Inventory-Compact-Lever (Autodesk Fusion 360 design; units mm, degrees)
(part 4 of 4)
work_plane "WorkPlane66" AlongDistance 54.9 ExtraOffset 0
sketch "Support-free horizontal rail hole roof" plane through (0, 0, 54.9) normal (0, 0, 1) x axis (1, 0, 0)
  line L1 (-28.0908, -83.0908) -> (-28.0908, -86.9092)
  line L2 (-26.1816, -85) -> (-28.0908, -83.0908)
  line L3 (-28.0908, -86.9092) -> (-26.1816, -85)
extrude "Extrude66" cut sketch "Support-free horizontal rail hole roof" along normal blind 9.2
work_plane "WorkPlane67" AlongDistance 54.9 ExtraOffset 0
sketch "Support-free horizontal rail hole roof (1)" plane through (0, 0, 54.9) normal (0, 0, 1) x axis (1, 0, 0)
  line L1 (-28.0908, 86.9092) -> (-28.0908, 83.0908)
  line L2 (-26.1816, 85) -> (-28.0908, 86.9092)
  line L3 (-28.0908, 83.0908) -> (-26.1816, 85)
extrude "Extrude67" cut sketch "Support-free horizontal rail hole roof (1)" along normal blind 9.2
work_plane "WorkPlane61" AlongDistance 54.9 ExtraOffset 0
sketch "Support-free horizontal rail hole roof" plane through (0, 0, 54.9) normal (0, 0, 1) x axis (1, 0, 0)
  line L1 (31.9092, -83.0908) -> (31.9092, -86.9092)
  line L2 (33.8184, -85) -> (31.9092, -83.0908)
  line L3 (31.9092, -86.9092) -> (33.8184, -85)
extrude "Extrude61" cut sketch "Support-free horizontal rail hole roof" along normal blind 9.2
work_plane "WorkPlane62" AlongDistance 54.9 ExtraOffset 0
sketch "Support-free horizontal rail hole roof (1)" plane through (0, 0, 54.9) normal (0, 0, 1) x axis (1, 0, 0)
  line L1 (31.9092, 86.9092) -> (31.9092, 83.0908)
  line L2 (33.8184, 85) -> (31.9092, 86.9092)
  line L3 (31.9092, 83.0908) -> (33.8184, 85)
extrude "Extrude62" cut sketch "Support-free horizontal rail hole roof (1)" along normal blind 9.2
work_plane "WorkPlane14" AlongDistance 4 ExtraOffset 0
sketch "Reinforced roof over support-free pivot bore" plane through (4, 0, 0) normal (1, 0, 0) x axis (0, 0, -1)
  line L1 (-17.9, -29) -> (-17.9, -41)
  line L2 (-20, -29) -> (-17.9, -29)
  line L3 (-20, -41) -> (-20, -29)
  line L4 (-17.9, -41) -> (-20, -41)
extrude "Extrude14" add sketch "Reinforced roof over support-free pivot bore" along normal blind 3
work_plane "WorkPlane15" AlongDistance 4 ExtraOffset 0
sketch "Flat print foot below roller cheek" plane through (4, 0, 0) normal (1, 0, 0) x axis (0, 0, -1)
  line L1 (-6, 6) -> (-6, -6)
  line L2 (-12, 6) -> (-6, 6)
  line L3 (-12, -6) -> (-12, 6)
  line L4 (-6, -6) -> (-12, -6)
extrude "Extrude15" add sketch "Flat print foot below roller cheek" along normal blind 3
work_plane "WorkPlane16" AlongDistance 17 ExtraOffset 0
sketch "Reinforced roof over support-free pivot bore (1)" plane through (17, 0, 0) normal (1, 0, 0) x axis (0, 0, -1)
  line L1 (-17.9, -29) -> (-17.9, -41)
  line L2 (-20, -29) -> (-17.9, -29)
  line L3 (-20, -41) -> (-20, -29)
  line L4 (-17.9, -41) -> (-20, -41)
extrude "Extrude16" add sketch "Reinforced roof over support-free pivot bore (1)" along normal blind 3
work_plane "WorkPlane17" AlongDistance 17 ExtraOffset 0
sketch "Flat print foot below roller cheek (1)" plane through (17, 0, 0) normal (1, 0, 0) x axis (0, 0, -1)
  line L1 (-6, 6) -> (-6, -6)
  line L2 (-12, 6) -> (-6, 6)
  line L3 (-12, -6) -> (-12, 6)
  line L4 (-6, -6) -> (-12, -6)
extrude "Extrude17" add sketch "Flat print foot below roller cheek (1)" along normal blind 3
work_plane "WorkPlane18" AlongDistance 3.9 ExtraOffset 0
sketch "Follower horizontal bore 45 degree roof" plane through (3.9, 0, 0) normal (1, 0, 0) x axis (0, 0, -1)
  line L1 (-14.9345, -32.0655) -> (-14.9345, -37.9345)
  line L2 (-17.869, -35) -> (-14.9345, -32.0655)
  line L3 (-14.9345, -37.9345) -> (-17.869, -35)
extrude "Extrude18" cut sketch "Follower horizontal bore 45 degree roof" along normal blind 16.2
work_plane "WorkPlane19" AlongDistance 3.9 ExtraOffset 0
sketch "Follower horizontal bore 45 degree roof (1)" plane through (3.9, 0, 0) normal (1, 0, 0) x axis (0, 0, -1)
  line L1 (-13.2021, 1.2021) -> (-13.2021, -1.2021)
  line L2 (-14.4042, 0) -> (-13.2021, 1.2021)
  line L3 (-13.2021, -1.2021) -> (-14.4042, 0)
extrude "Extrude19" cut sketch "Follower horizontal bore 45 degree roof (1)" along normal blind 16.2
work_plane "WorkPlane8" AlongDistance 49.65 ExtraOffset 0
sketch "Continuous support beneath lower output prong" plane through (49.65, 0, 0) normal (1, 0, 0) x axis (0, 0, -1)
  line L1 (-57, 2) -> (-57, -2)
  line L2 (-61, 2) -> (-57, 2)
  line L3 (-61, -2) -> (-61, 2)
  line L4 (-57, -2) -> (-61, -2)
extrude "Extrude8" add sketch "Continuous support beneath lower output prong" along normal blind 9
work_plane "WorkPlane11" AlongDistance 9 ExtraOffset 0
sketch "Upright grip head pocket roof" plane through (9, 0, 0) normal (1, 0, 0) x axis (0, 0, -1)
  line L1 (-182.192, -2.192) -> (-182.192, 2.192)
  line L2 (-184.3841, 0) -> (-182.192, -2.192)
  line L3 (-182.192, 2.192) -> (-184.3841, 0)
extrude "Extrude10" cut sketch "Upright grip head pocket roof" along normal blind 16
work_plane "WorkPlane12" AlongDistance 9 ExtraOffset 0
sketch "Upright grip head pocket roof (1)" plane through (9, 0, 0) normal (1, 0, 0) x axis (0, 0, -1)
  line L1 (-192.192, -2.192) -> (-192.192, 2.192)
  line L2 (-194.3841, 0) -> (-192.192, -2.192)
  line L3 (-192.192, 2.192) -> (-194.3841, 0)
extrude "Extrude11" cut sketch "Upright grip head pocket roof (1)" along normal blind 16
work_plane "WorkPlane11" AlongDistance -6.8 ExtraOffset 0
sketch "Shaft half joining insert pocket" plane through (0, -6.8, 0) normal (0, 1, 0) x axis (1, 0, 0)
  circle C1 centre (-15, -65) radius 2
extrude "Extrude11" cut sketch "Shaft half joining insert pocket" along normal blind 6.9
work_plane "WorkPlane12" AlongDistance -0.1 ExtraOffset 0
sketch "Shaft half joining screw clearance" plane through (0, -0.1, 0) normal (0, 1, 0) x axis (1, 0, 0)
  circle C1 centre (-15, -65) radius 1.7
extrude "Extrude12" cut sketch "Shaft half joining screw clearance" along normal blind 6.7
work_plane "WorkPlane13" AlongDistance 3.5 ExtraOffset 0
sketch "Flush shaft joining cap head" plane through (0, 3.5, 0) normal (0, 1, 0) x axis (1, 0, 0)
  circle C1 centre (-15, -65) radius 3.1
extrude "Extrude13" cut sketch "Flush shaft joining cap head" along normal blind 3.1
work_plane "WorkPlane1" AlongDistance -4.5 ExtraOffset 0
sketch "Shaft joining M3x8 -15" plane through (0, -4.5, 0) normal (0, 1, 0) x axis (1, 0, 0)
  circle C1 centre (-15, -65) radius 1.5
extrude "Extrude1" new body sketch "Shaft joining M3x8 -15" along normal blind 8 bodies "HARDWARE Shaft joining M3x8 -15"
work_plane "WorkPlane2" AlongDistance 3.5 ExtraOffset 0
sketch "Button head" plane through (0, 3.5, 0) normal (0, 1, 0) x axis (1, 0, 0)
  circle C1 centre (-15, -65) radius 2.75
extrude "Extrude2" add sketch "Button head" along normal blind 3
work_plane "WorkPlane14" AlongDistance -6.8 ExtraOffset 0
sketch "Shaft half joining insert pocket (1)" plane through (0, -6.8, 0) normal (0, 1, 0) x axis (1, 0, 0)
  circle C1 centre (15, -65) radius 2
extrude "Extrude14" cut sketch "Shaft half joining insert pocket (1)" along normal blind 6.9
work_plane "WorkPlane15" AlongDistance -0.1 ExtraOffset 0
sketch "Shaft half joining screw clearance (1)" plane through (0, -0.1, 0) normal (0, 1, 0) x axis (1, 0, 0)
  circle C1 centre (15, -65) radius 1.7
extrude "Extrude15" cut sketch "Shaft half joining screw clearance (1)" along normal blind 6.7
work_plane "WorkPlane16" AlongDistance 3.5 ExtraOffset 0
sketch "Flush shaft joining cap head (1)" plane through (0, 3.5, 0) normal (0, 1, 0) x axis (1, 0, 0)
  circle C1 centre (15, -65) radius 3.1
extrude "Extrude16" cut sketch "Flush shaft joining cap head (1)" along normal blind 3.1
work_plane "WorkPlane1" AlongDistance -4.5 ExtraOffset 0
sketch "Shaft joining M3x8 15" plane through (0, -4.5, 0) normal (0, 1, 0) x axis (1, 0, 0)
  circle C1 centre (15, -65) radius 1.5
extrude "Extrude1" new body sketch "Shaft joining M3x8 15" along normal blind 8 bodies "HARDWARE Shaft joining M3x8 15"
work_plane "WorkPlane2" AlongDistance 3.5 ExtraOffset 0
sketch "Button head" plane through (0, 3.5, 0) normal (0, 1, 0) x axis (1, 0, 0)
  circle C1 centre (15, -65) radius 2.75
extrude "Extrude2" add sketch "Button head" along normal blind 3
work_plane "WorkPlane17" AlongDistance -6.6 ExtraOffset 0
sketch "Loose alignment key pocket" plane through (-6.6, 0, 0) normal (1, 0, 0) x axis (0, 0, -1)
  line L1 (-61, 1.6) -> (-61, -1.6)
  line L2 (-69, 1.6) -> (-61, 1.6)
  line L3 (-69, -1.6) -> (-69, 1.6)
  line L4 (-61, -1.6) -> (-69, -1.6)
extrude "Extrude17" cut sketch "Loose alignment key pocket" along normal blind 3.2
work_plane "WorkPlane1" AlongDistance -6.5 ExtraOffset 0
sketch "Loose flat printable alignment key" plane through (-6.5, 0, 0) normal (1, 0, 0) x axis (0, 0, -1)
  line L1 (-61.1, 1.5) -> (-61.1, -1.5)
  line L2 (-68.9, 1.5) -> (-61.1, 1.5)
  line L3 (-68.9, -1.5) -> (-68.9, 1.5)
  line L4 (-61.1, -1.5) -> (-68.9, -1.5)
extrude "Extrude1" new body sketch "Loose flat printable alignment key" along normal blind 3 bodies "P28 Shaft alignment key -5"
work_plane "WorkPlane18" AlongDistance 3.4 ExtraOffset 0
sketch "Loose alignment key pocket (1)" plane through (3.4, 0, 0) normal (1, 0, 0) x axis (0, 0, -1)
  line L1 (-61, 1.6) -> (-61, -1.6)
  line L2 (-69, 1.6) -> (-61, 1.6)
  line L3 (-69, -1.6) -> (-69, 1.6)
  line L4 (-61, -1.6) -> (-69, -1.6)
extrude "Extrude18" cut sketch "Loose alignment key pocket (1)" along normal blind 3.2
work_plane "WorkPlane1" AlongDistance 3.5 ExtraOffset 0
sketch "Loose flat printable alignment key" plane through (3.5, 0, 0) normal (1, 0, 0) x axis (0, 0, -1)
  line L1 (-61.1, 1.5) -> (-61.1, -1.5)
  line L2 (-68.9, 1.5) -> (-61.1, 1.5)
  line L3 (-68.9, -1.5) -> (-68.9, 1.5)
  line L4 (-61.1, -1.5) -> (-68.9, -1.5)
extrude "Extrude1" new body sketch "Loose flat printable alignment key" along normal blind 3 bodies "P28 Shaft alignment key 5"
split "Split1" bodies "P05 Shaft upper half"
work_plane "WorkPlane19" AlongDistance -5 ExtraOffset 0
sketch "Direct cap-head rotor clamp seat" plane through (-5, 0, 0) normal (1, 0, 0) x axis (0, 0, -1)
  line L1 (-60, 22.5) -> (-60, 22)
  line L2 (-70, 22.5) -> (-60, 22.5)
  line L3 (-70, 22) -> (-70, 22.5)
  line L4 (-60, 22) -> (-70, 22)
extrude "Extrude19" add sketch "Direct cap-head rotor clamp seat" along normal blind 10
work_plane "WorkPlane20" AlongDistance 21.9 ExtraOffset 0
sketch "Restore rotor screw through raised seat" plane through (0, 21.9, 0) normal (0, 1, 0) x axis (1, 0, 0)
  circle C1 centre (0, -65) radius 1.7
extrude "Extrude20" cut sketch "Restore rotor screw through raised seat" along normal blind 0.7
work_plane "WorkPlane1" AlongDistance -39.35 ExtraOffset 0
sketch "Main shaft cap M3x8 cap head" plane through (-39.35, 0, 0) normal (1, 0, 0) x axis (0, 0, -1)
  circle C1 centre (-65, 0) radius 1.5
extrude "Extrude1" new body sketch "Main shaft cap M3x8 cap head" along normal blind 8 bodies "HARDWARE Main shaft cap M3x8 cap head"
work_plane "WorkPlane2" AlongDistance -42.35 ExtraOffset 0
sketch "Button head" plane through (-42.35, 0, 0) normal (1, 0, 0) x axis (0, 0, -1)
  circle C1 centre (-65, 0) radius 2.75
extrude "Extrude2" add sketch "Button head" along normal blind 3
work_plane "WorkPlane1" AlongDistance 2 ExtraOffset 0
sketch "Cam M3x10 cap head -45" plane through (2, 0, 0) normal (1, 0, 0) x axis (0, 0, -1)
  circle C1 centre (-39.5442, 25.4558) radius 1.5
extrude "Extrude1" new body sketch "Cam M3x10 cap head -45" along normal blind 10 bodies "HARDWARE Cam M3x10 cap head -45"
work_plane "WorkPlane2" AlongDistance 12 ExtraOffset 0
sketch "Button head" plane through (12, 0, 0) normal (1, 0, 0) x axis (0, 0, -1)
  circle C1 centre (-39.5442, 25.4558) radius 2.75
extrude "Extrude2" add sketch "Button head" along normal blind 3
work_plane "WorkPlane1" AlongDistance 2 ExtraOffset 0
sketch "Cam M3x10 cap head 0" plane through (2, 0, 0) normal (1, 0, 0) x axis (0, 0, -1)
  circle C1 centre (-29, 0) radius 1.5
extrude "Extrude1" new body sketch "Cam M3x10 cap head 0" along normal blind 10 bodies "HARDWARE Cam M3x10 cap head 0"
work_plane "WorkPlane2" AlongDistance 12 ExtraOffset 0
sketch "Button head" plane through (12, 0, 0) normal (1, 0, 0) x axis (0, 0, -1)
  circle C1 centre (-29, 0) radius 2.75
extrude "Extrude2" add sketch "Button head" along normal blind 3
work_plane "WorkPlane1" AlongDistance 2 ExtraOffset 0
sketch "Cam M3x10 cap head 45" plane through (2, 0, 0) normal (1, 0, 0) x axis (0, 0, -1)
  circle C1 centre (-39.5442, -25.4558) radius 1.5
extrude "Extrude1" new body sketch "Cam M3x10 cap head 45" along normal blind 10 bodies "HARDWARE Cam M3x10 cap head 45"
work_plane "WorkPlane2" AlongDistance 12 ExtraOffset 0
sketch "Button head" plane through (12, 0, 0) normal (1, 0, 0) x axis (0, 0, -1)
  circle C1 centre (-39.5442, -25.4558) radius 2.75
extrude "Extrude2" add sketch "Button head" along normal blind 3
work_plane "WorkPlane1" AlongDistance 0 ExtraOffset 0
sketch "Roller axle M3x20 cap head" plane through (0, 0, 0) normal (1, 0, 0) x axis (0, 0, -1)
  circle C1 centre (-12, 0) radius 1.5
extrude "Extrude1" new body sketch "Roller axle M3x20 cap head" along normal blind 20 bodies "HARDWARE Roller axle M3x20 cap head"
work_plane "WorkPlane2" AlongDistance 20 ExtraOffset 0
sketch "Button head" plane through (20, 0, 0) normal (1, 0, 0) x axis (0, 0, -1)
  circle C1 centre (-12, 0) radius 2.75
extrude "Extrude2" add sketch "Button head" along normal blind 3
work_plane "WorkPlane1" AlongDistance -36 ExtraOffset 0
sketch "Crossblock M3x20 cap head (-62, -1)" plane through (-36, 0, 0) normal (1, 0, 0) x axis (0, 0, -1)
  circle C1 centre (-53.5, -62) radius 1.5
extrude "Extrude1" new body sketch "Crossblock M3x20 cap head (-62, -1)" along normal blind 20 bodies "HARDWARE Crossblock M3x20 cap head (-62, -1)"
work_plane "WorkPlane2" AlongDistance -39 ExtraOffset 0
sketch "Button head" plane through (-39, 0, 0) normal (1, 0, 0) x axis (0, 0, -1)
  circle C1 centre (-53.5, -62) radius 2.75
extrude "Extrude2" add sketch "Button head" along normal blind 3
work_plane "WorkPlane1" AlongDistance 16 ExtraOffset 0
sketch "Crossblock M3x20 cap head (-62, 1)" plane through (16, 0, 0) normal (1, 0, 0) x axis (0, 0, -1)
  circle C1 centre (-53.5, -62) radius 1.5
extrude "Extrude1" new body sketch "Crossblock M3x20 cap head (-62, 1)" along normal blind 20 bodies "HARDWARE Crossblock M3x20 cap head (-62, 1)"
work_plane "WorkPlane2" AlongDistance 36 ExtraOffset 0
sketch "Button head" plane through (36, 0, 0) normal (1, 0, 0) x axis (0, 0, -1)
  circle C1 centre (-53.5, -62) radius 2.75
extrude "Extrude2" add sketch "Button head" along normal blind 3
work_plane "WorkPlane1" AlongDistance -36 ExtraOffset 0
sketch "Crossblock M3x20 cap head (-70, -1)" plane through (-36, 0, 0) normal (1, 0, 0) x axis (0, 0, -1)
  circle C1 centre (-53.5, -70) radius 1.5
extrude "Extrude1" new body sketch "Crossblock M3x20 cap head (-70, -1)" along normal blind 20 bodies "HARDWARE Crossblock M3x20 cap head (-70, -1)"
work_plane "WorkPlane2" AlongDistance -39 ExtraOffset 0
sketch "Button head" plane through (-39, 0, 0) normal (1, 0, 0) x axis (0, 0, -1)
  circle C1 centre (-53.5, -70) radius 2.75
extrude "Extrude2" add sketch "Button head" along normal blind 3
work_plane "WorkPlane1" AlongDistance 16 ExtraOffset 0
sketch "Crossblock M3x20 cap head (-70, 1)" plane through (16, 0, 0) normal (1, 0, 0) x axis (0, 0, -1)
  circle C1 centre (-53.5, -70) radius 1.5
extrude "Extrude1" new body sketch "Crossblock M3x20 cap head (-70, 1)" along normal blind 20 bodies "HARDWARE Crossblock M3x20 cap head (-70, 1)"
work_plane "WorkPlane2" AlongDistance 36 ExtraOffset 0
sketch "Button head" plane through (36, 0, 0) normal (1, 0, 0) x axis (0, 0, -1)
  circle C1 centre (-53.5, -70) radius 2.75
extrude "Extrude2" add sketch "Button head" along normal blind 3
work_plane "WorkPlane1" AlongDistance 6.5 ExtraOffset 0
sketch "Rotor clamp M3x16 cap head" plane through (0, 6.5, 0) normal (0, 1, 0) x axis (1, 0, 0)
  circle C1 centre (0, -65) radius 1.5
extrude "Extrude1" new body sketch "Rotor clamp M3x16 cap head" along normal blind 16 bodies "HARDWARE Rotor clamp M3x16 cap head"
work_plane "WorkPlane2" AlongDistance 22.5 ExtraOffset 0
sketch "Button head" plane through (0, 22.5, 0) normal (0, 1, 0) x axis (1, 0, 0)
  circle C1 centre (0, -65) radius 2.75
extrude "Extrude2" add sketch "Button head" along normal blind 3
work_plane "WorkPlane20" AlongDistance 3.9 ExtraOffset 0
sketch "Restore axle bore after adding print feet" plane through (3.9, 0, 0) normal (1, 0, 0) x axis (0, 0, -1)
  circle C1 centre (-12, 0) radius 1.7
extrude "Extrude20" cut sketch "Restore axle bore after adding print feet" along normal blind 16.2
work_plane "WorkPlane21" AlongDistance 3.9 ExtraOffset 0
sketch "Restore nut installation recess after print foot" plane through (3.9, 0, 0) normal (1, 0, 0) x axis (0, 0, -1)
  line L1 (-14.9, 1.6743) -> (-12, 3.3486)
  line L2 (-14.9, -1.6743) -> (-14.9, 1.6743)
  line L3 (-12, -3.3486) -> (-14.9, -1.6743)
  line L4 (-9.1, -1.6743) -> (-12, -3.3486)
  line L5 (-9.1, 1.6743) -> (-9.1, -1.6743)
  line L6 (-12, 3.3486) -> (-9.1, 1.6743)
extrude "Extrude21" cut sketch "Restore nut installation recess after print foot" along normal blind 1.6
work_plane "WorkPlane3" AlongDistance 8 ExtraOffset 0
sketch "Retain one mm preload travel before head meets collar" plane through (8, 0, 0) normal (1, 0, 0) x axis (0, 0, -1)
  line L1 (-56, -51) -> (-56, -59)
  line L2 (-57.1, -51) -> (-56, -51)
  line L3 (-57.1, -59) -> (-57.1, -51)
  line L4 (-56, -59) -> (-57.1, -59)
extrude "Extrude3" cut sketch "Retain one mm preload travel before head meets collar" along normal blind 8
work_plane "WorkPlane63" AlongDistance 20.8 ExtraOffset 0
sketch "Clear stocked carriage screw tip beyond insert" plane through (0, 20.8, 0) normal (0, 1, 0) x axis (1, 0, 0)
  circle C1 centre (60.15, -65) radius 1.7
extrude "Extrude63" cut sketch "Clear stocked carriage screw tip beyond insert" along normal blind 0.6
work_plane "WorkPlane64" AlongDistance -21.4 ExtraOffset 0
sketch "Clear stocked carriage screw tip beyond insert (1)" plane through (0, -21.4, 0) normal (0, 1, 0) x axis (1, 0, 0)
  circle C1 centre (60.15, -65) radius 1.7
extrude "Extrude64" cut sketch "Clear stocked carriage screw tip beyond insert (1)" along normal blind 0.6
work_plane "WorkPlane22" AlongDistance -2.5 ExtraOffset 0
sketch "Support-free lower ramp under left inner-race pad" plane through (0, -2.5, 0) normal (0, 1, 0) x axis (1, 0, 0)
  line L1 (8.1, -9.5) -> (7, -9.5)
  line L2 (8.1, -10.7) -> (8.1, -9.5)
  line L3 (7, -9.6) -> (8.1, -10.7)
  line L4 (7, -9.5) -> (7, -9.6)
extrude "Extrude22" cut sketch "Support-free lower ramp under left inner-race pad" along normal blind 5
work_plane "WorkPlane23" AlongDistance -2.5 ExtraOffset 0
sketch "Support-free lower ramp under right inner-race pad" plane through (0, -2.5, 0) normal (0, 1, 0) x axis (1, 0, 0)
  line L1 (17, -9.5) -> (15.9, -9.5)
  line L2 (17, -9.6) -> (17, -9.5)
  line L3 (15.9, -10.7) -> (17, -9.6)
  line L4 (15.9, -9.5) -> (15.9, -10.7)
extrude "Extrude23" cut sketch "Support-free lower ramp under right inner-race pad" along normal blind 5
ground "Pin94"
ground "Pin95"
ground "Pin96"
ground "Pin97"
ground "Pin98"
ground "Pin99"
ground "Pin100"
ground "Pin101"
ground "Pin102"
ground "Pin103"
ground "Pin104"
ground "Pin105"
ground "Pin106"
ground "Pin107"
ground "Pin108"
ground "Pin109"
ground "Pin110"
ground "Pin111"
ground "Pin112"
ground "Pin113"
ground "Pin114"
ground "Pin115"
ground "Pin116"
ground "Pin117"
ground "Pin118"
ground "Pin119"
ground "Pin120"
ground "Pin121"
ground "Pin122"
ground "Pin123"
as_built_joint "As-built11"
as_built_joint "As-built12"
as_built_joint "As-built13" RotateMinimum -52 RotateMaximum 52
as_built_joint "As-built14" RotateMinimum -6 RotateMaximum 1
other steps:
create_component "CreateComponent1"
create_component "CreateComponent2"
create_component "CreateComponent3"
create_component "CreateComponent4"
create_component "CreateComponent5"
create_component "CreateComponent6"
create_component "CreateComponent7"
create_component "CreateComponent8"
create_component "CreateComponent9"
create_component "CreateComponent10"
create_component "CreateComponent11"
create_component "CreateComponent12"
create_component "CreateComponent13"
create_component "CreateComponent14"
create_component "CreateComponent16"
create_component "CreateComponent28"
create_component "CreateComponent29"
create_component "CreateComponent49"
create_component "CreateComponent89"
create_component "CreateComponent90"
create_component "CreateComponent140"
create_component "CreateComponent141"
create_component "CreateComponent142"
create_component "CreateComponent143"
create_component "CreateComponent144"
create_component "CreateComponent145"
create_component "CreateComponent146"
create_component "CreateComponent147"
create_component "CreateComponent148"
create_component "CreateComponent149"
create_component "CreateComponent150"
create_component "CreateComponent151"
create_component "CreateComponent152"
create_component "CreateComponent153"
create_component "CreateComponent154"
create_component "CreateComponent155"
create_component "CreateComponent156"
create_component "CreateComponent157"
create_component "CreateComponent158"
create_component "CreateComponent159"
create_component "CreateComponent160"
create_component "CreateComponent161"
create_component "CreateComponent162"
create_component "CreateComponent163"
create_component "CreateComponent164"
create_component "CreateComponent165"
create_component "CreateComponent166"
create_component "CreateComponent167"
create_component "CreateComponent168"
create_component "CreateComponent169"
create_component "CreateComponent170"
create_component "CreateComponent171"
create_component "CreateComponent172"
create_component "CreateComponent173"
create_component "CreateComponent174"
create_component "CreateComponent175"
create_component "CreateComponent176"
create_component "CreateComponent177"
create_component "CreateComponent178"
create_component "CreateComponent179"
create_component "CreateComponent180"
create_component "CreateComponent181"
create_component "CreateComponent182"
create_component "CreateComponent183"
create_component "CreateComponent184"
named bodies: "P01 Left rail sideplate", "P02 Right rail sideplate", "P03 Left flanged journal bush", "P04 Right flanged journal bush", "P05 Shaft lower half", "P06 Shaft retaining cap", "P07 Integral lever rotor and cam carrier", "P08 Cam 7 gates - stable endpoints", "P08 Cam 5 gates - stable endpoints", "P08 Cam 3 gates - stable endpoints", "P09 Grip insert half", "P10 Grip screw half", "P11 Forked roller follower", "P13 Spring reaction crossblock", "P21 Follower left axial spacer", "P22 Follower right axial spacer", "HARDWARE Roller axle M3 nut", "P23 Left rotor thrust spacer", "P24 Right rotor thrust spacer", "HARDWARE Rail M5x14 DIN912 (-30, -1)", "HARDWARE Rail M5x14 DIN912 (-30, 1)", "HARDWARE Rail M5x14 DIN912 (30, -1)", "HARDWARE Rail M5x14 DIN912 (30, 1)", "P25 Captured printed pivot lower half", "P26 Captured printed pivot upper half", "HARDWARE Grip M3x20 cap head 180", "HARDWARE Grip M3x20 cap head 190", "HARDWARE Stop M3x20 cap head -1", "HARDWARE Stop M3 plain captive nut -1", "HARDWARE Stop M3x20 cap head 1", "HARDWARE Stop M3 plain captive nut 1", "HARDWARE 623ZZ roller bearing at 8", "HARDWARE 623ZZ roller bearing at 12", "P27 Printed guide sleeve 4", "HARDWARE Cup guide M3x12 4", "P27 Printed guide sleeve 20", "HARDWARE Cup guide M3x12 20", "P14 Captive spring cup for 9 mm spring", "P15 Recessed preload limit collar 1 mm", "HARDWARE Preload M3x20 cap head", "REFERENCE Stock spring OD9 wire1 free20 - rate and solid height assumed", "P16 Compact adjustable RK097 mount", "HARDWARE Compact carriage M3x12 -1", "HARDWARE Compact carriage M3x12 1", "P18 Compact floating coupling disc", "P19 Compact one-piece sensor clamp", "HARDWARE Compact sensor clamp M3x16", "REFERENCE RK097 provisional compact envelope - measure before fit", "HARDWARE RK097 supplied washer ASSUMED", "HARDWARE RK097 supplied nut ASSUMED", "HARDWARE Shaft joining M3x8 -15", "HARDWARE Shaft joining M3x8 15", "P28 Shaft alignment key -5", "P28 Shaft alignment key 5", "P05 Shaft upper half", "HARDWARE Main shaft cap M3x8 cap head", "HARDWARE Cam M3x10 cap head -45", "HARDWARE Cam M3x10 cap head 0", "HARDWARE Cam M3x10 cap head 45", "HARDWARE Roller axle M3x20 cap head"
